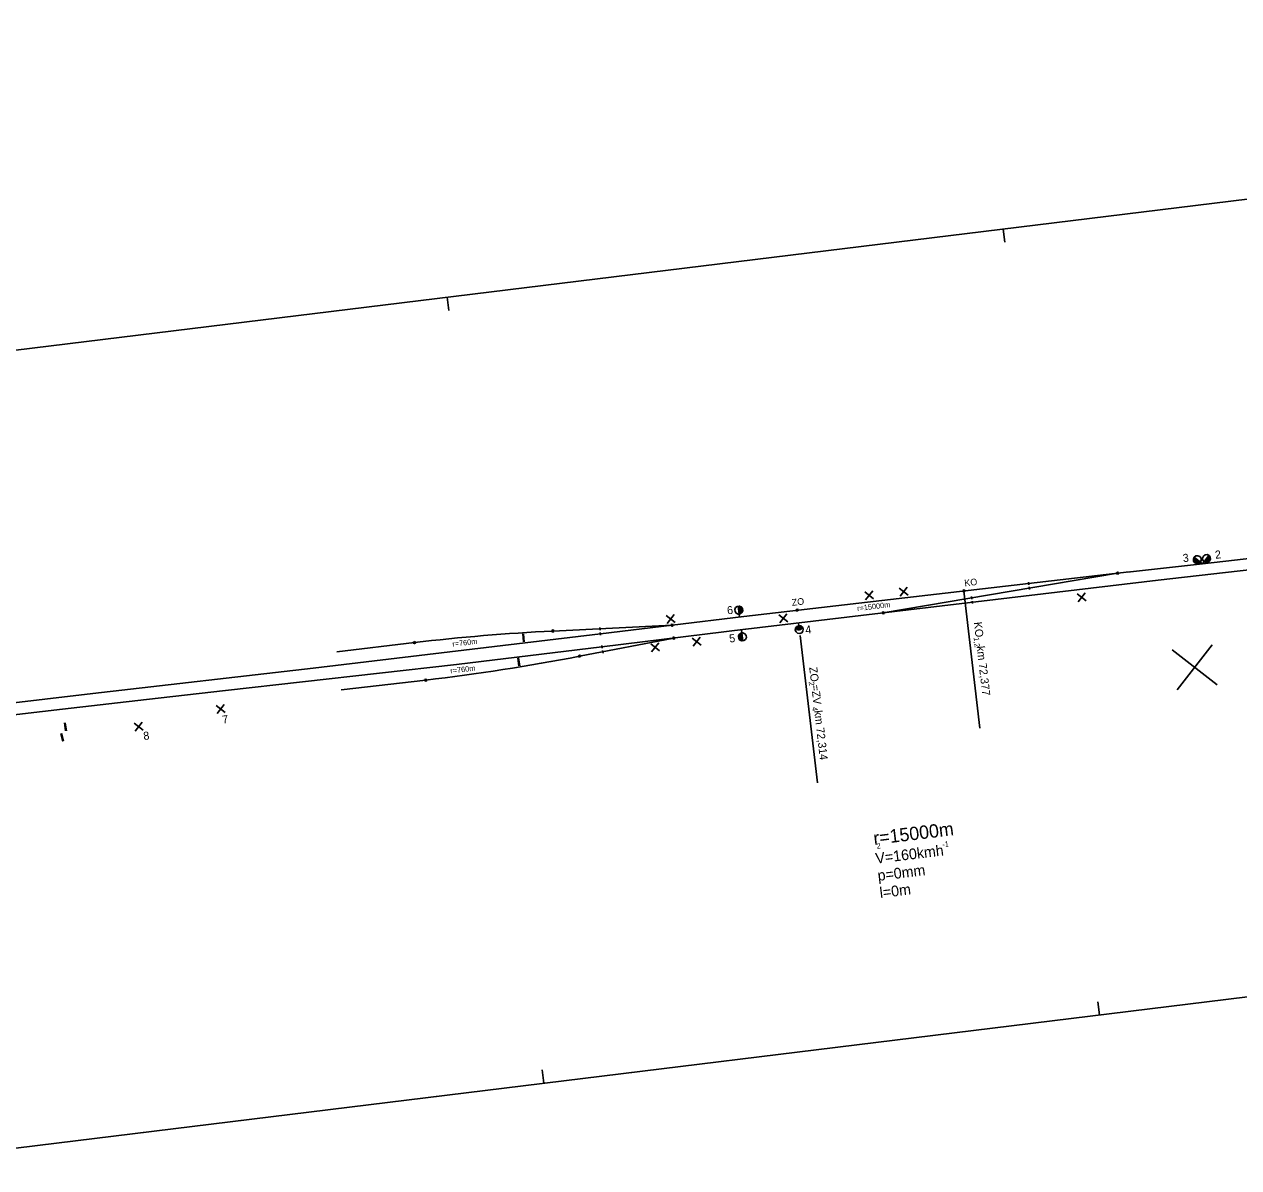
# Model space of a CAD drawing. Extents: x -559083 to -556962, y -1276579 to -1276028.
# Drawn here: x -557990.7 to -557535.4, y -1276456.8 to -1276027.9 of the extents above; entities that cross this region are included whole.
import ezdxf

# ---------------------------------------------------------------- set-up
doc = ezdxf.new("R2010")
doc.units = 0
for name, color, linetype in [('kolaj s', 7, 'Continuous'), ('popis 25', 7, 'Continuous'), ('popis 50', 7, 'Continuous'), ('ram vykresu', 7, 'Continuous')]:
    doc.layers.add(name, color=color, linetype=linetype)

msp = doc.modelspace()

# ---------------------------------------------------------------- linework, layer by layer
at = {"layer": 'kolaj s'}
for p, q in [((-557548.94, -1276230.25), (-557503.36, -1276224.98)), ((-557577.1, -1276233.39), (-557548.94, -1276230.25)), ((-557498.35, -1276228.64), (-557565.52, -1276236.4)), ((-557720.87, -1276250.01), (-557576.5, -1276233.32)), ((-557565.52, -1276236.4), (-557720.22, -1276254.83)), ((-557668.63, -1276248.68), (-557580.77, -1276233.81)), ((-557580.77, -1276233.81), (-557580.77, -1276233.81)), ((-557638.4, -1276240.47), (-557638.4, -1276240.47)), ((-557614.22, -1276237.17), (-557614.1, -1276238.16)), ((-557614.16, -1276237.67), (-557614.16, -1276237.67)), ((-557613.97, -1276238.92), (-557613.85, -1276239.91)), ((-557613.91, -1276239.41), (-557613.91, -1276239.41)), ((-557635.55, -1276242.57), (-557635.43, -1276243.56)), ((-557635.49, -1276243.07), (-557635.49, -1276243.07)), ((-557635.31, -1276244.22), (-557635.19, -1276245.21)), ((-557635.25, -1276244.71), (-557635.25, -1276244.71)), ((-557774.69, -1276256.53), (-557720.87, -1276250.01)), ((-557700.9, -1276247.68), (-557700.9, -1276247.68)), ((-557668.63, -1276248.68), (-557668.63, -1276248.68)), ((-557747.78, -1276253.27), (-557792.53, -1276255.47)), ((-557774.83, -1276255.1), (-557774.88, -1276254.1)), ((-557774.85, -1276254.6), (-557774.85, -1276254.6)), ((-557774.12, -1276261.35), (-557720.29, -1276254.84)), ((-557747.78, -1276253.27), (-557747.78, -1276253.27)), ((-557774.69, -1276256.53), (-557882.46, -1276269.35)), ((-557873.49, -1276263.24), (-557844.45, -1276259.81)), ((-557844.45, -1276259.81), (-557844.45, -1276259.81)), ((-557792.53, -1276255.47), (-557792.53, -1276255.47)), ((-557747.2, -1276258.1), (-557782.52, -1276264.95)), ((-557774.63, -1276257.02), (-557774.75, -1276256.03)), ((-557774.69, -1276256.53), (-557774.69, -1276256.53)), ((-557747.2, -1276258.1), (-557747.2, -1276258.1)), ((-557828.6, -1276268), (-557774.12, -1276261.35)), ((-557774.06, -1276261.85), (-557774.18, -1276260.86)), ((-557774.12, -1276261.35), (-557774.12, -1276261.35)), ((-557773.72, -1276263.75), (-557773.91, -1276262.77)), ((-557773.82, -1276263.26), (-557773.82, -1276263.26)), ((-557915.23, -1276277.78), (-557828.6, -1276268)), ((-557782.52, -1276264.95), (-557782.52, -1276264.95)), ((-557882.46, -1276269.35), (-557965.05, -1276278.93)), ((-557944.87, -1276281.15), (-557915.23, -1276277.78)), ((-557840.2, -1276273.86), (-557871.88, -1276277.52)), ((-557840.2, -1276273.86), (-557840.2, -1276273.86)), ((-557965.05, -1276278.93), (-558049.14, -1276288.8)), ((-557976.35, -1276284.79), (-557944.87, -1276281.15)), ((-558007.88, -1276288.49), (-557976.35, -1276284.79))]:
    msp.add_line(p, q, dxfattribs=at)
for points in [[(-557580.72, -1276234.21), (-557581.09, -1276234.05), (-557581.14, -1276233.66), (-557580.82, -1276233.41), (-557580.45, -1276233.57), (-557580.4, -1276233.97), (-557580.72, -1276234.21)], [(-557638.35, -1276240.87), (-557638.71, -1276240.71), (-557638.76, -1276240.32), (-557638.45, -1276240.07), (-557638.08, -1276240.23), (-557638.03, -1276240.63), (-557638.35, -1276240.87)], [(-557700.85, -1276248.07), (-557701.21, -1276247.92), (-557701.26, -1276247.52), (-557700.95, -1276247.28), (-557700.58, -1276247.44), (-557700.53, -1276247.83), (-557700.85, -1276248.07)], [(-557668.58, -1276249.08), (-557668.95, -1276248.92), (-557669, -1276248.53), (-557668.68, -1276248.29), (-557668.31, -1276248.44), (-557668.26, -1276248.84), (-557668.58, -1276249.08)], [(-557792.51, -1276255.87), (-557792.86, -1276255.69), (-557792.88, -1276255.29), (-557792.55, -1276255.07), (-557792.19, -1276255.26), (-557792.17, -1276255.65), (-557792.51, -1276255.87)], [(-557747.79, -1276252.87), (-557747.44, -1276253.06), (-557747.43, -1276253.46), (-557747.76, -1276253.67), (-557748.12, -1276253.48), (-557748.13, -1276253.08), (-557747.79, -1276252.87)], [(-557844.5, -1276259.41), (-557844.13, -1276259.57), (-557844.09, -1276259.97), (-557844.41, -1276260.21), (-557844.78, -1276260.05), (-557844.82, -1276259.65), (-557844.5, -1276259.41)], [(-557747.22, -1276257.7), (-557746.87, -1276257.88), (-557746.85, -1276258.28), (-557747.19, -1276258.5), (-557747.54, -1276258.31), (-557747.56, -1276257.91), (-557747.22, -1276257.7)], [(-557782.44, -1276265.34), (-557782.82, -1276265.21), (-557782.89, -1276264.82), (-557782.59, -1276264.56), (-557782.21, -1276264.69), (-557782.14, -1276265.08), (-557782.44, -1276265.34)], [(-557840.25, -1276273.47), (-557839.88, -1276273.62), (-557839.84, -1276274.02), (-557840.16, -1276274.26), (-557840.52, -1276274.1), (-557840.57, -1276273.71), (-557840.25, -1276273.47)]]:
    msp.add_lwpolyline(points, dxfattribs=at)
for centre, start, end in [((-557755.21, -1277014.55), 92.81429, 96.74331), ((-557927.32, -1275518.87), 276.58261, 280.98426)]:
    msp.add_arc(centre, 760, start, end, dxfattribs=at)
at = {"layer": 'popis 25'}
for p, q in [((-557803.83, -1276256.56), (-557803.55, -1276259.54)), ((-557803.51, -1276256.53), (-557803.24, -1276259.51)), ((-557805.7, -1276265.6), (-557805.23, -1276268.55)), ((-557805.38, -1276265.55), (-557804.91, -1276268.51)), ((-557975.65, -1276289.96), (-557975.24, -1276292.92)), ((-557975.34, -1276289.91), (-557974.93, -1276292.88)), ((-557977.03, -1276293.94), (-557976.29, -1276296.84)), ((-557976.72, -1276293.86), (-557975.98, -1276296.76))]:
    msp.add_line(p, q, dxfattribs=at)
at = {"layer": 'popis 50'}
for p, q in [((-557548.94, -1276230.25), (-557548.94, -1276230.25)), ((-557672.26, -1276243.39), (-557675.61, -1276240.74)), ((-557672.61, -1276240.38), (-557675.26, -1276243.74)), ((-557659.28, -1276241.99), (-557662.64, -1276239.34)), ((-557659.64, -1276238.99), (-557662.28, -1276242.34)), ((-557632.43, -1276291.94), (-557638.38, -1276240.47)), ((-557592.52, -1276244.13), (-557595.88, -1276241.48)), ((-557592.88, -1276241.12), (-557595.52, -1276244.48)), ((-557746.65, -1276252.28), (-557750.01, -1276249.63)), ((-557747.01, -1276249.28), (-557749.65, -1276252.63)), ((-557722.52, -1276250.12), (-557723, -1276246.2)), ((-557722.52, -1276250.12), (-557722.52, -1276250.12)), ((-557704.38, -1276252.04), (-557707.75, -1276249.41)), ((-557704.75, -1276249.04), (-557707.38, -1276252.41)), ((-557721.75, -1276255.19), (-557721.75, -1276255.19)), ((-557721.75, -1276255.19), (-557721.27, -1276259.11)), ((-557701.62, -1276255.14), (-557701.52, -1276254.37)), ((-557701.36, -1276255.84), (-557701.62, -1276255.14)), ((-557701.52, -1276254.37), (-557701.08, -1276253.79)), ((-557701.13, -1276254.17), (-557700.86, -1276253.94)), ((-557701.05, -1276254.85), (-557701.13, -1276254.17)), ((-557701.08, -1276253.79), (-557700.31, -1276253.47)), ((-557700.31, -1276253.47), (-557701.08, -1276253.78)), ((-557700.86, -1276253.94), (-557700.73, -1276254.98)), ((-557700.57, -1276253.8), (-557700.31, -1276253.47)), ((-557700.42, -1276255.04), (-557700.57, -1276253.8)), ((-557700.43, -1276252.47), (-557700.31, -1276253.47)), ((-557700.31, -1276253.47), (-557699.49, -1276253.58)), ((-557699.98, -1276253.73), (-557700.31, -1276253.47)), ((-557700.31, -1276253.47), (-557700.12, -1276255.03)), ((-557700.31, -1276253.47), (-557700.12, -1276255.03)), ((-557699.82, -1276254.97), (-557699.98, -1276253.73)), ((-557699.34, -1276253.95), (-557699.67, -1276253.79)), ((-557699.67, -1276253.79), (-557699.54, -1276254.84)), ((-557699.49, -1276253.58), (-557698.95, -1276254.05)), ((-557699.26, -1276254.63), (-557699.34, -1276253.95)), ((-557698.95, -1276254.05), (-557698.64, -1276254.77)), ((-557698.64, -1276254.77), (-557698.75, -1276255.49)), ((-557736.96, -1276260.84), (-557740.32, -1276258.19)), ((-557737.32, -1276257.84), (-557739.96, -1276261.2)), ((-557700.77, -1276256.32), (-557701.36, -1276255.84)), ((-557699.95, -1276256.44), (-557700.77, -1276256.32)), ((-557699.18, -1276256.11), (-557699.95, -1276256.44)), ((-557693.36, -1276312.35), (-557699.74, -1276257.18)), ((-557698.75, -1276255.49), (-557699.18, -1276256.11)), ((-557752.48, -1276262.9), (-557755.84, -1276260.25)), ((-557752.84, -1276259.89), (-557755.48, -1276263.25)), ((-557543.42, -1276275.63), (-557560.26, -1276262.47)), ((-557545.26, -1276260.63), (-557558.42, -1276277.47)), ((-557915.45, -1276286.06), (-557918.81, -1276283.42)), ((-557915.81, -1276283.06), (-557918.45, -1276286.42)), ((-557946.17, -1276292.62), (-557949.53, -1276289.98)), ((-557946.53, -1276289.62), (-557949.17, -1276292.98))]:
    msp.add_line(p, q, dxfattribs=at)
for points in [[(-557549.71, -1276229.65), (-557549.41, -1276228.93), (-557549.5, -1276228.16), (-557549.97, -1276227.54), (-557550.69, -1276227.24), (-557551.45, -1276227.33), (-557552.08, -1276227.8), (-557552.38, -1276228.52), (-557552.28, -1276229.29), (-557551.82, -1276229.91), (-557551.1, -1276230.21), (-557550.33, -1276230.12), (-557549.71, -1276229.65), (-557550.09, -1276229.53), (-557550.48, -1276230.03), (-557550.88, -1276230.08), (-557550.35, -1276229.42), (-557550.58, -1276229.19), (-557551.19, -1276230.02), (-557551.5, -1276229.91), (-557550.81, -1276229.02), (-557551.03, -1276228.84), (-557551.78, -1276229.74), (-557551.95, -1276229.51), (-557551.26, -1276228.62), (-557551.48, -1276228.45), (-557552.09, -1276229.23), (-557552.19, -1276228.83), (-557551.75, -1276228.28), (-557551.98, -1276228.05), (-557552.2, -1276228.33)], [(-557552.06, -1276227.81), (-557548.94, -1276230.25), (-557546.51, -1276227.13)], [(-557546.5, -1276227.12), (-557547.21, -1276226.81), (-557547.98, -1276226.91), (-557548.63, -1276227.41), (-557548.91, -1276228.09), (-557548.81, -1276228.86), (-557548.34, -1276229.48), (-557547.63, -1276229.78), (-557546.86, -1276229.69), (-557546.27, -1276229.26), (-557545.93, -1276228.51), (-557546.03, -1276227.74), (-557546.5, -1276227.12), (-557546.56, -1276227.49), (-557546.17, -1276227.79), (-557546.12, -1276228.24), (-557546.73, -1276227.76), (-557546.9, -1276227.98), (-557546.12, -1276228.59), (-557546.24, -1276228.91), (-557547.13, -1276228.21), (-557547.3, -1276228.49), (-557546.41, -1276229.13), (-557546.63, -1276229.36), (-557547.47, -1276228.71), (-557547.64, -1276228.93), (-557546.86, -1276229.54), (-557547.31, -1276229.59), (-557547.87, -1276229.16), (-557548.04, -1276229.38), (-557547.71, -1276229.64)], [(-557722.6, -1276246.15), (-557723.4, -1276246.25), (-557724.01, -1276246.71), (-557724.31, -1276247.42), (-557724.21, -1276248.21), (-557723.75, -1276248.82), (-557723.05, -1276249.12), (-557722.25, -1276249.03), (-557721.64, -1276248.56), (-557721.34, -1276247.86), (-557721.43, -1276247.06), (-557721.9, -1276246.45), (-557722.6, -1276246.15), (-557722.33, -1276246.36), (-557722.82, -1276246.43), (-557722.79, -1276246.72), (-557721.94, -1276246.62), (-557721.76, -1276246.9), (-557722.75, -1276247.02), (-557722.71, -1276247.32), (-557721.57, -1276247.18), (-557721.53, -1276247.48), (-557722.68, -1276247.62), (-557722.64, -1276247.92), (-557721.5, -1276247.78), (-557721.61, -1276248.09), (-557722.6, -1276248.21), (-557722.57, -1276248.51), (-557721.72, -1276248.41), (-557722.08, -1276248.75), (-557722.53, -1276248.81)], [(-557721.67, -1276259.16), (-557720.87, -1276259.06), (-557720.26, -1276258.6), (-557719.96, -1276257.89), (-557720.06, -1276257.1), (-557720.52, -1276256.49), (-557721.26, -1276256.18), (-557722.01, -1276256.28), (-557722.63, -1276256.75), (-557722.93, -1276257.45), (-557722.84, -1276258.25), (-557722.37, -1276258.85), (-557721.67, -1276259.16), (-557721.94, -1276258.94), (-557721.45, -1276258.88), (-557721.48, -1276258.58), (-557722.33, -1276258.69), (-557722.56, -1276258.41), (-557721.52, -1276258.29), (-557721.56, -1276257.99), (-557722.7, -1276258.13), (-557722.74, -1276257.83), (-557721.59, -1276257.69), (-557721.63, -1276257.39), (-557722.77, -1276257.53), (-557722.66, -1276257.22), (-557721.67, -1276257.09), (-557721.7, -1276256.8), (-557722.55, -1276256.9), (-557722.19, -1276256.55), (-557721.74, -1276256.5)]]:
    msp.add_lwpolyline(points, dxfattribs=at)
msp.add_arc((-557700.3, -1276253.55), 1.5, 215.2276, 338.7724, dxfattribs=at)
at = {"layer": 'ram vykresu'}
for p, q in [((-558090.24, -1276161.98), (-556998.42, -1276027.92)), ((-557623.11, -1276109.66), (-557623.72, -1276104.7)), ((-557831.55, -1276135.25), (-557832.16, -1276130.29)), ((-556962.22, -1276322.7), (-558054.04, -1276456.76)), ((-557587.53, -1276399.48), (-557588.14, -1276394.52)), ((-557795.96, -1276425.07), (-557796.57, -1276420.11))]:
    msp.add_line(p, q, dxfattribs=at)

# ---------------------------------------------------------------- texts
at = {"layer": 'popis 25'}
for s, height, rotation, p in [('KO', 2.5, 7, (-557638.08, -1276238.77)), ('ZO', 2.5, 7, (-557702.78, -1276246.05)), ('r=15000m', 2, 6.8, (-557678.33, -1276248)), ('r=760m', 2, 6.8, (-557830.11, -1276261.38)), ('r=760m', 2, 6.8, (-557830.87, -1276271.42))]:
    msp.add_text(s, height=height, rotation=rotation, dxfattribs=at).set_placement(p)
at = {"layer": 'popis 50'}
for s, height, rotation, p in [('3', 3, 7, (-557556.15, -1276229.67)), ('2', 3, 7, (-557544.07, -1276228.42)), ('6', 3, 7, (-557727.03, -1276249.24)), ('4', 3, 7, (-557697.68, -1276256.54)), ('KO   km 72,377', 3, 276.5971, (-557634.68, -1276252.21)), ('5', 3, 7, (-557726.22, -1276259.82)), ('1,2', 2, 276.5971, (-557634.76, -1276257.89)), ('ZO =ZV  km 72,314', 3, 276.5971, (-557696.41, -1276269.12)), ('2', 2, 276.5971, (-557696.61, -1276274.54)), ('7', 3, 7, (-557916.29, -1276290.23)), ('4', 2, 276.5971, (-557695.34, -1276284.08)), ('8', 3, 7, (-557945.88, -1276296.36)), ('r=15000m', 5, 7, (-557672.05, -1276335.72)), ('V=160kmh', 4, 7, (-557671.33, -1276342.75)), ('2', 2, 7, (-557671.01, -1276337.17)), ('-1', 2, 7, (-557646.38, -1276336.54)), ('p=0mm', 4, 7, (-557670.54, -1276349.2)), ('l=0m', 4, 7, (-557669.74, -1276355.65))]:
    msp.add_text(s, height=height, rotation=rotation, dxfattribs=at).set_placement(p)

doc.saveas('drawing.dxf')
